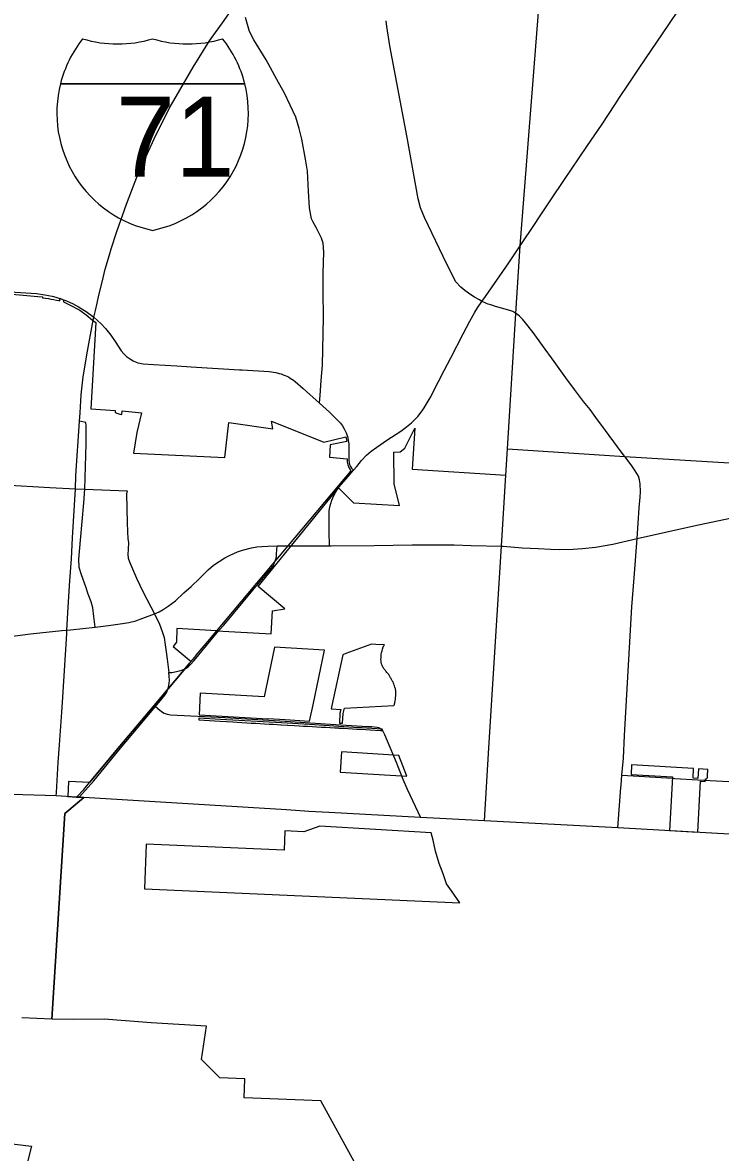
# Model space of a CAD drawing. Extents: x 1729596 to 1925846, y 659247 to 911751.
# Drawn here: x 1836127 to 1847054, y 772373 to 790063 of the extents above; entities that cross this region are included whole.
import ezdxf

# ---------------------------------------------------------------- set-up
doc = ezdxf.new("R2010")
doc.units = 0
for name, color, linetype in [('GM_X_City_Street', 7, 'Continuous'), ('GM_X_Corporation', 7, 'Continuous'), ('GM_X_County', 7, 'Continuous'), ('GM_X_County_Road', 7, 'Continuous'), ('GM_X_Interstate_Route', 7, 'Continuous'), ('GM_X_Interstate_Shield', 7, 'Continuous'), ('GM_X_State_Route', 7, 'Continuous'), ('GM_X_Township', 7, 'Continuous'), ('GM_X_Township_Road', 7, 'Continuous')]:
    doc.layers.add(name, color=color, linetype=linetype)

msp = doc.modelspace()

# ---------------------------------------------------------------- linework, layer by layer
at = {"layer": 'GM_X_City_Street'}
for points in [[(1845795, 782632), (1845801, 782714), (1845799, 782843), (1845789, 782905), (1845769, 782961), (1845719, 783045), (1845654, 783136), (1845556, 783268), (1845531, 783302)], [(1835705, 782831), (1835839, 782824), (1836553, 782786), (1836955, 782764), (1837100, 782758), (1837765, 782732)], [(1837765, 782732), (1837753, 782682), (1837765, 782232), (1837770, 782095)], [(1840933, 781871), (1840926, 782090), (1840925, 782331), (1840928, 782415), (1840938, 782483), (1840967, 782584), (1840998, 782659), (1841047, 782741), (1841072, 782775)], [(1845750, 781984), (1845750, 781984), (1845784, 782465), (1845795, 782632)], [(1845750, 781984), (1846636, 782185), (1847206, 782302), (1847513, 782368), (1847786, 782434), (1847977, 782469), (1848131, 782490), (1848273, 782507), (1848502, 782514), (1848624, 782515), (1848801, 782501), (1849017, 782481), (1849162, 782462), (1849304, 782438), (1849411, 782418), (1849555, 782383), (1849710, 782340), (1849838, 782298), (1850003, 782242)], [(1837770, 782095), (1837775, 781981), (1837783, 781922), (1837779, 781819), (1837777, 781733), (1837782, 781676), (1837802, 781618), (1837814, 781583), (1837912, 781362), (1838015, 781147), (1838193, 780805)], [(1843653, 781863), (1843947, 781841), (1844201, 781827), (1844395, 781817), (1844535, 781814), (1844750, 781817), (1844893, 781827), (1845099, 781849), (1845367, 781896), (1845750, 781984)], [(1845701, 781367), (1845750, 781984)], [(1837262, 780598), (1837472, 780623), (1837692, 780652), (1837788, 780671), (1837899, 780697), (1838012, 780736), (1838193, 780805), (1838267, 780838), (1838327, 780874), (1838407, 780927), (1838522, 781011), (1838653, 781132), (1838768, 781235), (1838897, 781361), (1839033, 781492), (1839117, 781565), (1839207, 781627), (1839292, 781682), (1839379, 781723), (1839494, 781774), (1839571, 781804), (1839711, 781841), (1839792, 781854), (1839873, 781862), (1839966, 781866), (1840114, 781870)], [(1840090, 781659), (1840100, 781698), (1840105, 781743), (1840114, 781870)], [(1840114, 781870), (1840114, 781870), (1840273, 781870)], [(1840378, 781870), (1840933, 781871), (1840960, 781871)], [(1840960, 781871), (1841634, 781878), (1842225, 781888), (1842619, 781888), (1842884, 781888), (1843152, 781878), (1843626, 781866), (1843653, 781863)], [(1843361, 777564), (1843430, 778709), (1843626, 781866)], [(1845497, 778125), (1845512, 778280), (1845535, 778545), (1845550, 778898), (1845665, 780916), (1845701, 781367)], [(1838193, 780805), (1838268, 780643), (1838314, 780527), (1838341, 780436), (1838361, 780322), (1838379, 780175), (1838390, 780094), (1838419, 779886)], [(1838675, 779950), (1838679, 779951), (1838721, 779977), (1838758, 780012), (1838814, 780076), (1839202, 780542)], [(1838398, 779616), (1838413, 779659), (1838423, 779716), (1838425, 779769), (1838424, 779828), (1838419, 779886)], [(1838419, 779886), (1838461, 779889), (1838582, 779913), (1838619, 779924), (1838675, 779950)], [(1837662, 778703), (1837938, 779032), (1838207, 779353), (1838312, 779478), (1838354, 779530), (1838378, 779568), (1838391, 779594), (1838398, 779616)], [(1838207, 779353), (1838276, 779296), (1838316, 779268), (1838343, 779249), (1838391, 779233), (1838445, 779226), (1839292, 779180), (1840238, 779123), (1841028, 779074), (1841530, 779043), (1841590, 779040), (1841681, 779032), (1841706, 779026), (1841723, 779017), (1841743, 779001)], [(1841743, 779001), (1841743, 779001), (1841760, 778978), (1841792, 778916), (1841834, 778818), (1841974, 778482)], [(1837011, 777935), (1837067, 777991), (1837241, 778192), (1837519, 778532), (1837662, 778703)], [(1846702, 778207), (1847381, 778168), (1847556, 778157), (1847623, 778159), (1847653, 778187), (1847668, 778222), (1847673, 778281), (1847683, 778338), (1847722, 778457)], [(1842083, 778219), (1842149, 778061), (1842358, 777614)], [(1845512, 778280), (1846301, 778231), (1846340, 778229)], [(1845449, 777453), (1845493, 778084), (1845497, 778125)]]:
    msp.add_lwpolyline(points, dxfattribs=at)
at = {"layer": 'GM_X_Corporation'}
for points in [[(1835905, 785817), (1836363, 785772), (1836439, 785767), (1836438, 785752), (1836485, 785747), (1836530, 785742), (1836571, 785735), (1836613, 785728), (1836656, 785718), (1836693, 785710), (1836710, 785705), (1836712, 785746), (1836743, 785733), (1836768, 785721), (1836766, 785689), (1836880, 785635), (1837022, 785558), (1837123, 785488), (1837222, 785404), (1837273, 785365), (1837194, 784015), (1837577, 783991), (1837574, 783956), (1837620, 783941), (1837650, 783930), (1837681, 783927), (1837687, 783984), (1837990, 783954), (1837918, 783644), (1837865, 783321), (1839293, 783253), (1839358, 783800), (1840047, 783704), (1840026, 783821), (1840842, 783494), (1841189, 783579), (1841206, 783505), (1840944, 783454), (1840934, 783259), (1841208, 783235), (1841210, 783181), (1841220, 783138), (1841242, 783087), (1841269, 783047), (1841184, 782945), (1840280, 781871), (1839165, 780541), (1838544, 780578), (1838538, 780363), (1838485, 780296), (1838765, 780060), (1838745, 780037), (1838742, 780031), (1838725, 780013), (1838668, 779945), (1838625, 779894), (1838186, 779371), (1837650, 778732), (1837174, 778163), (1836848, 778182), (1836833, 777945), (1836973, 777937), (1837085, 777931), (1836852, 777733), (1836789, 777680), (1836587, 774459), (1836117, 774478)], [(1841326, 772218), (1840796, 773182), (1839597, 773227), (1839608, 773527), (1839213, 773542), (1838929, 773828), (1839006, 774350), (1838141, 774402), (1837403, 774461), (1836916, 774455), (1836587, 774459), (1836789, 777680), (1836852, 777733), (1837085, 777931), (1836973, 777937), (1836974, 777938), (1837086, 778057), (1837174, 778163), (1837650, 778732), (1838186, 779371), (1838625, 779894), (1838668, 779945), (1838725, 780013), (1838742, 780031), (1838745, 780037), (1838765, 780060), (1838767, 780058), (1838846, 780153), (1838843, 780156), (1838968, 780306), (1838971, 780303), (1839170, 780540), (1840019, 780491), (1840040, 780852), (1840233, 780886), (1839815, 781235), (1841073, 782777), (1841309, 782546), (1842031, 782501), (1841945, 782843), (1841941, 783336), (1842037, 783342), (1842114, 783400), (1842268, 783711), (1842228, 783073), (1843694, 782979), (1843719, 783387), (1845556, 783268), (1847880, 783128)], [(1835872, 772517), (1836265, 772469), (1836073, 771716)]]:
    msp.add_lwpolyline(points, dxfattribs=at)
for points in [[(1840970, 779369), (1840959, 779320), (1841110, 779309), (1841096, 779248), (1841087, 779095), (1841138, 779092), (1841146, 779243), (1841165, 779331), (1841942, 779371), (1841944, 779376), (1841948, 779388), (1841951, 779398), (1841955, 779413), (1841955, 779414), (1841958, 779426), (1841959, 779436), (1841960, 779440), (1841966, 779468), (1841967, 779474), (1841967, 779484), (1841968, 779496), (1841968, 779507), (1841969, 779514), (1841970, 779522), (1841971, 779532), (1841971, 779535), (1841971, 779551), (1841970, 779593), (1841970, 779603), (1841968, 779613), (1841966, 779626), (1841964, 779635), (1841962, 779639), (1841955, 779659), (1841950, 779678), (1841946, 779691), (1841939, 779707), (1841934, 779717), (1841932, 779723), (1841928, 779732), (1841922, 779745), (1841916, 779757), (1841900, 779787), (1841897, 779793), (1841890, 779804), (1841884, 779814), (1841866, 779846), (1841864, 779849), (1841859, 779856), (1841855, 779862), (1841851, 779865), (1841847, 779870), (1841844, 779872), (1841835, 779883), (1841831, 779888), (1841820, 779903), (1841814, 779910), (1841809, 779917), (1841798, 779927), (1841797, 779929), (1841790, 779938), (1841782, 779950), (1841776, 779959), (1841773, 779964), (1841771, 779969), (1841769, 779972), (1841768, 779975), (1841761, 779987), (1841759, 779993), (1841756, 780002), (1841754, 780006), (1841749, 780017), (1841747, 780021), (1841745, 780025), (1841745, 780027), (1841742, 780036), (1841742, 780044), (1841740, 780055), (1841740, 780061), (1841740, 780063), (1841740, 780070), (1841738, 780090), (1841738, 780093), (1841738, 780099), (1841739, 780112), (1841740, 780136), (1841740, 780140), (1841741, 780150), (1841743, 780164), (1841744, 780176), (1841748, 780194), (1841749, 780200), (1841752, 780208), (1841752, 780210), (1841756, 780227), (1841761, 780247), (1841762, 780250), (1841764, 780257), (1841766, 780263), (1841768, 780271), (1841770, 780276), (1841772, 780283), (1841774, 780288), (1841777, 780293), (1841779, 780298), (1841783, 780304), (1841785, 780307), (1841788, 780313), (1841789, 780316), (1841792, 780320), (1841659, 780327), (1841589, 780331), (1841190, 780184), (1841140, 780165)], [(1838890, 779225), (1839969, 779163), (1839969, 779168), (1840239, 779153), (1840620, 779123), (1840675, 779380), (1840855, 780239), (1840069, 780286), (1839907, 779506), (1838909, 779563)], [(1838888, 779170), (1838887, 779146), (1839222, 779126), (1839417, 779112), (1839487, 779108), (1839562, 779104), (1839637, 779100), (1839707, 779096), (1839777, 779092), (1839847, 779088), (1839917, 779084), (1839987, 779080), (1840057, 779076), (1840172, 779069), (1840174, 779069), (1840277, 779063), (1840280, 779063), (1840386, 779057), (1840456, 779053), (1840526, 779049), (1840595, 779045), (1840665, 779041), (1840735, 779037), (1840805, 779033), (1840874, 779029), (1840944, 779025), (1841014, 779021), (1841079, 779018), (1841081, 779017), (1841083, 779017), (1841153, 779013), (1841156, 779013), (1841158, 779013), (1841223, 779009), (1841292, 779006), (1841362, 779002), (1841432, 778998), (1841501, 778994), (1841571, 778990), (1841732, 778980), (1841765, 778979), (1841755, 779000), (1841675, 779005), (1841439, 779020), (1841311, 779027), (1841080, 779042), (1840617, 779071), (1840183, 779097), (1839224, 779152)], [(1841118, 778645), (1841099, 778328), (1842145, 778266), (1842016, 778588)], [(1846859, 778368), (1846710, 778378), (1846702, 778229), (1846625, 778234), (1846634, 778383), (1845663, 778439), (1845654, 778289), (1846303, 778254), (1846258, 777411), (1846699, 777386), (1846740, 778185), (1846816, 778181), (1846819, 778221), (1846824, 778221), (1846830, 778222), (1846834, 778223), (1846838, 778226), (1846842, 778229), (1846846, 778234), (1846848, 778239), (1846850, 778244), (1846851, 778248), (1846852, 778267)], [(1838033, 776502), (1842974, 776280), (1842842, 776467), (1842767, 776576), (1842710, 776732), (1842648, 776896), (1842594, 777087), (1842556, 777259), (1842523, 777374), (1840783, 777481), (1840533, 777392), (1840233, 777406), (1840220, 777106), (1838064, 777201)]]:
    msp.add_lwpolyline(points, close=True, dxfattribs=at)
at = {"layer": 'GM_X_County'}
msp.add_lwpolyline([(1855849, 776844), (1854746, 776908), (1853977, 776957), (1851228, 777114), (1851193, 777116), (1850903, 777132), (1850744, 777141), (1850569, 777151), (1848580, 777271), (1848276, 777289), (1848085, 777300), (1847560, 777333), (1845449, 777453), (1843361, 777564), (1842358, 777614), (1840924, 777694), (1840611, 777712), (1840257, 777736), (1837085, 777931), (1837011, 777935), (1836973, 777937), (1836651, 777955), (1835956, 777979)], dxfattribs=at)
at = {"layer": 'GM_X_County_Road'}
for points in [[(1843969, 786645), (1844100, 786841), (1844260, 787083), (1844407, 787305), (1844600, 787588), (1844962, 788122), (1845200, 788475), (1845400, 788775), (1845475, 788889), (1845613, 789100), (1845780, 789348), (1846245, 790032), (1846408, 790272)], [(1843318, 785694), (1843279, 785722), (1843205, 785766), (1843131, 785811), (1843049, 785869), (1842990, 785919), (1842913, 786003), (1842770, 786283), (1842422, 787009), (1842359, 787165), (1842321, 787304), (1842151, 788263), (1841879, 789699), (1841828, 790004), (1841819, 790093)], [(1842589, 784346), (1842634, 784434), (1842728, 784617), (1842832, 784814), (1843028, 785192), (1843132, 785389), (1843208, 785531), (1843250, 785597), (1843318, 785694), (1843374, 785774), (1843742, 786301), (1843918, 786568), (1843969, 786645)], [(1830137, 786102), (1830408, 786127), (1830473, 786131), (1830595, 786143), (1830674, 786150), (1830727, 786150), (1830805, 786149), (1831205, 786125), (1831840, 786089), (1832575, 786043), (1833895, 785967), (1834638, 785924), (1835200, 785890), (1836012, 785840), (1836343, 785821), (1836473, 785802), (1836589, 785781), (1836648, 785764), (1836710, 785745), (1836767, 785724)], [(1836767, 785724), (1836786, 785717), (1836824, 785700)], [(1836824, 785700), (1836909, 785663), (1837004, 785613), (1837124, 785539), (1837243, 785449), (1837357, 785344), (1837425, 785273), (1837506, 785171), (1837585, 785055), (1837672, 784921), (1837711, 784875), (1837731, 784855), (1837753, 784836), (1837800, 784801), (1837815, 784791), (1837856, 784768), (1837907, 784747), (1837933, 784738), (1837960, 784731), (1837988, 784725), (1838015, 784721), (1838179, 784709), (1838542, 784687), (1838768, 784673), (1839525, 784627), (1839566, 784625), (1839988, 784599), (1840024, 784595), (1840057, 784590), (1840091, 784584), (1840142, 784571), (1840175, 784561), (1840207, 784550), (1840239, 784537), (1840288, 784514), (1840316, 784498), (1840369, 784463), (1840394, 784443), (1840518, 784334), (1840776, 784103), (1840930, 783961), (1841001, 783894), (1841068, 783830), (1841103, 783792), (1841135, 783749), (1841164, 783700), (1841192, 783642), (1841213, 783581), (1841227, 783525), (1841231, 783496), (1841234, 783467), (1841236, 783438), (1841235, 783218), (1841240, 783168), (1841245, 783146), (1841249, 783135), (1841259, 783112), (1841275, 783087), (1841308, 783054)], [(1843915, 785461), (1843910, 785466), (1843876, 785495), (1843850, 785510), (1843805, 785538), (1843756, 785553), (1843625, 785594), (1843533, 785620), (1843488, 785634), (1843403, 785662), (1843358, 785678), (1843318, 785694)], [(1845531, 783302), (1845441, 783422), (1845252, 783676), (1845103, 783878), (1845012, 784005), (1844911, 784131), (1844769, 784320), (1844631, 784501), (1844451, 784757), (1844268, 785009), (1844121, 785212), (1843999, 785361), (1843954, 785418), (1843915, 785461)], [(1842518, 784205), (1842589, 784346)], [(1841308, 783054), (1841360, 783114), (1841434, 783206), (1841511, 783291), (1841584, 783354), (1841672, 783417), (1841829, 783524), (1842048, 783668), (1842113, 783713), (1842218, 783797), (1842316, 783897), (1842383, 783983), (1842415, 784029), (1842495, 784159), (1842518, 784205)], [(1841072, 782775), (1841086, 782794), (1841225, 782955), (1841308, 783054)], [(1840273, 781870), (1840318, 781870), (1840378, 781870)], [(1840053, 781560), (1840062, 781581), (1840072, 781607), (1840088, 781652), (1840090, 781659)], [(1839781, 781234), (1839795, 781251), (1839953, 781436), (1840049, 781552), (1840053, 781560)], [(1839202, 780542), (1839276, 780630), (1839733, 781176), (1839781, 781234)]]:
    msp.add_lwpolyline(points, dxfattribs=at)
at = {"layer": 'GM_X_Interstate_Route'}
for points in [[(1837487, 786429), (1837514, 786520), (1837601, 786793), (1837756, 787221), (1837932, 787687), (1838187, 788245), (1838424, 788716), (1838589, 789007), (1838800, 789367), (1839053, 789775), (1839282, 790094), (1839487, 790389), (1839554, 790475), (1839800, 790800), (1840096, 791202), (1840599, 791880), (1841473, 793063), (1842402, 794310), (1842953, 795035), (1844609, 797255), (1845106, 797922), (1845407, 798332)], [(1837267, 785553), (1837294, 785668), (1837323, 785796), (1837371, 786001), (1837421, 786203), (1837487, 786429)], [(1837223, 785347), (1837233, 785398), (1837243, 785449), (1837267, 785553)], [(1837020, 783821), (1837027, 783953), (1837045, 784237), (1837075, 784514), (1837141, 784917), (1837223, 785347)], [(1836817, 780494), (1836820, 780550), (1836840, 780909), (1836868, 781322), (1836890, 781668), (1836906, 781995), (1836955, 782764), (1836962, 782965), (1837020, 783821)], [(1836705, 778752), (1836739, 779265), (1836749, 779422), (1836817, 780494)], [(1836655, 778007), (1836686, 778478), (1836705, 778752)], [(1836651, 777955), (1836655, 778007)]]:
    msp.add_lwpolyline(points, dxfattribs=at)
at = {"layer": 'GM_X_Interstate_Shield'}
for p, q in [((1836721, 789106), (1839606, 789106)), ((1839606, 789106), (1836721, 789106)), ((1839606, 789106), (1836721, 789106)), ((1836721, 789106), (1839606, 789106)), ((1839606, 789106), (1836721, 789106)), ((1839606, 789106), (1836721, 789106))]:
    msp.add_line(p, q, dxfattribs=at)
for centre, start, end in [((1838538, 788647), 141.669, 165.8066), ((1838538, 788647), 141.669, 165.8066), ((1837615, 791603), 253.0091, 286.9909), ((1837615, 791603), 253.0091, 286.9909), ((1838711, 791603), 253.0091, 286.9909), ((1838711, 791603), 253.0091, 286.9909), ((1837788, 788647), 14.1934, 38.331), ((1837788, 788647), 14.1934, 38.331), ((1838538, 788647), 165.8066, 258.463), ((1838538, 788647), 165.8066, 258.463), ((1837788, 788647), 281.537, 14.1934), ((1837788, 788647), 281.537, 14.1934)]:
    msp.add_arc(centre, 1875, start, end, dxfattribs=at)
at = {"layer": 'GM_X_State_Route'}
for points in [[(1837100, 782758), (1837122, 783468), (1837121, 783747), (1837119, 783802), (1837020, 783821)], [(1837005, 781660), (1837033, 781960), (1837087, 782544), (1837100, 782758)], [(1837262, 780598), (1837243, 780763), (1837224, 780898), (1837199, 780995), (1837156, 781115), (1837115, 781226), (1837051, 781415), (1837014, 781532), (1837005, 781660)], [(1835722, 780425), (1836249, 780492), (1836397, 780507)], [(1836397, 780507), (1836740, 780542), (1836820, 780550), (1836877, 780557), (1837262, 780598)]]:
    msp.add_lwpolyline(points, dxfattribs=at)
at = {"layer": 'GM_X_Township'}
msp.add_lwpolyline([(1843361, 777564), (1843430, 778709), (1843626, 781866), (1843694, 782979), (1843719, 783387), (1843850, 785510), (1843918, 786568), (1844278, 791160)], dxfattribs=at)
at = {"layer": 'GM_X_Township_Road'}
for points in [[(1840776, 784103), (1840783, 784165), (1840786, 784226), (1840804, 784460), (1840825, 784699), (1840840, 785445), (1840831, 785855), (1840833, 786147), (1840842, 786466), (1840835, 786609), (1840806, 786690), (1840723, 786857), (1840679, 786939), (1840648, 786992), (1840620, 787160), (1840605, 787423), (1840587, 787735), (1840557, 787925), (1840498, 788237), (1840457, 788405), (1840405, 788583), (1840228, 788959), (1840110, 789170), (1839941, 789478), (1839747, 789795), (1839679, 789921), (1839616, 790145)], [(1841974, 778482), (1842083, 778219)], [(1846340, 778229), (1846702, 778207)]]:
    msp.add_lwpolyline(points, dxfattribs=at)

# ---------------------------------------------------------------- texts
at = {"layer": 'GM_X_Interstate_Shield'}
msp.add_text('71', height=1250, dxfattribs=at).set_placement((1837586, 787653))
msp.add_text('71', height=1250, dxfattribs=at).set_placement((1837586, 787653))

doc.saveas('drawing.dxf')
